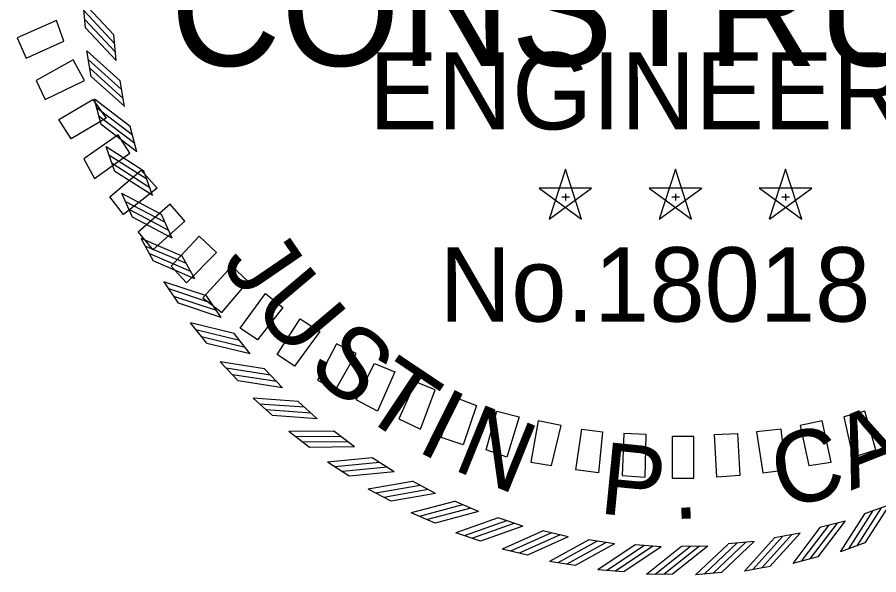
# Model space of a CAD drawing. Extents: x 16 to 1228743, y 11 to 152440.
# Drawn here: x 17.6697 to 17.7949, y 10.8149 to 10.8959 of the extents above; entities that cross this region are included whole.
import ezdxf

# ---------------------------------------------------------------- set-up
doc = ezdxf.new("R2010")
doc.units = 0
doc.layers.add('STAMP_JUSTIN', color=7, linetype='Continuous')
doc.layers.add('STAMP_PRELIM', color=7, linetype='Continuous')

msp = doc.modelspace()

# ---------------------------------------------------------------- linework, layer by layer
at = {"layer": 'STAMP_JUSTIN'}
for p, q in [((17.67966, 10.89435), (17.67932, 10.8981)), ((17.68413, 10.88959), (17.68378, 10.89335)), ((17.68051, 10.88729), (17.67985, 10.891)), ((17.68535, 10.88292), (17.6847, 10.88664)), ((17.68193, 10.88033), (17.68097, 10.88397)), ((17.68712, 10.87637), (17.68616, 10.88003)), ((17.68392, 10.87351), (17.68267, 10.87706)), ((17.68942, 10.86999), (17.68816, 10.87356)), ((17.74939, 10.87381), (17.74703, 10.86658)), ((17.75174, 10.86658), (17.74939, 10.87382)), ((17.76538, 10.87381), (17.76302, 10.86658)), ((17.76773, 10.86658), (17.76539, 10.87382)), ((17.78137, 10.87381), (17.77901, 10.86658)), ((17.78372, 10.86658), (17.78138, 10.87382)), ((17.75319, 10.87105), (17.74558, 10.87106)), ((17.74559, 10.87105), (17.75174, 10.86657)), ((17.74704, 10.86658), (17.7532, 10.87105)), ((17.76918, 10.87105), (17.76157, 10.87106)), ((17.76158, 10.87105), (17.76773, 10.86657)), ((17.76303, 10.86658), (17.76919, 10.87105)), ((17.78517, 10.87105), (17.77756, 10.87106)), ((17.77757, 10.87105), (17.78372, 10.86657)), ((17.77902, 10.86658), (17.78518, 10.87105)), ((17.68647, 10.86687), (17.68493, 10.87031)), ((17.74885, 10.86983), (17.74998, 10.86983)), ((17.7494, 10.87024), (17.7494, 10.86928)), ((17.76484, 10.86983), (17.76597, 10.86983)), ((17.76539, 10.87024), (17.76539, 10.86928)), ((17.78083, 10.86983), (17.78196, 10.86983)), ((17.78138, 10.87024), (17.78138, 10.86928)), ((17.69224, 10.86383), (17.69069, 10.86727)), ((17.68956, 10.86047), (17.68774, 10.86377)), ((17.69556, 10.85791), (17.69373, 10.86122)), ((17.69317, 10.85435), (17.69108, 10.85749)), ((17.69936, 10.85229), (17.69726, 10.85544)), ((17.69727, 10.84855), (17.69492, 10.8515)), ((17.70361, 10.84701), (17.70126, 10.84997)), ((17.70183, 10.8431), (17.69925, 10.84585)), ((17.70828, 10.84209), (17.70569, 10.84485)), ((17.70683, 10.83805), (17.70403, 10.84058)), ((17.71334, 10.83758), (17.71054, 10.84011)), ((17.71223, 10.83343), (17.70923, 10.83572)), ((17.71875, 10.83349), (17.71575, 10.83579)), ((17.71799, 10.82927), (17.71482, 10.8313)), ((17.72449, 10.82987), (17.72131, 10.83191)), ((17.7305, 10.82674), (17.72716, 10.82851)), ((17.72408, 10.8256), (17.72075, 10.82736)), ((17.73676, 10.82411), (17.73328, 10.8256)), ((17.7964, 10.82504), (17.79284, 10.82378)), ((17.73045, 10.82245), (17.72698, 10.82393)), ((17.7432, 10.82201), (17.73962, 10.8232)), ((17.79002, 10.82274), (17.78637, 10.82178)), ((17.73705, 10.81983), (17.73348, 10.82102)), ((17.7498, 10.82045), (17.74613, 10.82134)), ((17.78348, 10.82097), (17.77976, 10.82032)), ((17.75651, 10.81944), (17.75278, 10.82002)), ((17.77681, 10.81975), (17.77304, 10.81941)), ((17.74386, 10.81777), (17.74019, 10.81866)), ((17.76328, 10.81898), (17.75951, 10.81926)), ((17.77006, 10.81909), (17.76628, 10.81905)), ((17.79289, 10.81955), (17.78934, 10.81829)), ((17.78607, 10.81755), (17.78242, 10.81659)), ((17.7508, 10.81627), (17.74708, 10.81686)), ((17.77911, 10.81613), (17.77539, 10.81548)), ((17.75785, 10.81536), (17.75409, 10.81564)), ((17.76495, 10.81503), (17.76118, 10.81499)), ((17.77205, 10.81529), (17.7683, 10.81494))]:
    msp.add_line(p, q, dxfattribs=at)
for points in [[(17.68378, 10.89335), (17.67932, 10.8981)], [(17.68389, 10.8921), (17.67942, 10.89685)], [(17.68404, 10.8908), (17.67957, 10.89555)], [(17.68414, 10.88959), (17.67967, 10.89434)], [(17.68469, 10.88664), (17.67985, 10.89101)], [(17.6849, 10.8854), (17.68006, 10.88977)], [(17.68516, 10.88411), (17.68031, 10.88848)], [(17.68536, 10.88292), (17.68051, 10.88729)], [(17.68616, 10.88002), (17.68097, 10.88398)], [(17.68646, 10.8788), (17.68128, 10.88276)], [(17.68683, 10.87755), (17.68164, 10.8815)], [(17.68712, 10.87637), (17.68194, 10.88032)], [(17.68816, 10.87355), (17.68266, 10.87706)], [(17.68857, 10.87236), (17.68307, 10.87588)], [(17.68903, 10.87114), (17.68353, 10.87465)], [(17.68943, 10.86999), (17.68393, 10.8735)], [(17.69069, 10.86727), (17.68492, 10.87031)], [(17.6912, 10.86612), (17.68543, 10.86916)], [(17.69176, 10.86494), (17.68599, 10.86798)], [(17.69225, 10.86382), (17.68648, 10.86687)], [(17.69373, 10.86121), (17.68773, 10.86377)], [(17.69433, 10.86011), (17.68833, 10.86267)], [(17.69499, 10.85898), (17.68899, 10.86154)], [(17.69557, 10.85791), (17.68957, 10.86047)], [(17.69726, 10.85543), (17.69107, 10.85749)], [(17.69795, 10.85438), (17.69176, 10.85644)], [(17.6987, 10.85331), (17.69251, 10.85536)], [(17.69936, 10.85229), (17.69317, 10.85435)], [(17.70126, 10.84996), (17.69492, 10.8515)], [(17.70203, 10.84897), (17.69569, 10.85051)], [(17.70287, 10.84796), (17.69653, 10.8495)], [(17.70361, 10.84701), (17.69727, 10.84854)], [(17.70569, 10.84484), (17.69925, 10.84585)], [(17.70654, 10.84392), (17.7001, 10.84493)], [(17.70746, 10.84298), (17.70102, 10.84399)], [(17.70828, 10.84209), (17.70184, 10.8431)], [(17.71054, 10.8401), (17.70403, 10.84058)], [(17.71146, 10.83925), (17.70495, 10.83973)], [(17.71245, 10.8384), (17.70595, 10.83887)], [(17.71334, 10.83758), (17.70684, 10.83805)], [(17.71575, 10.83578), (17.70923, 10.83572)], [(17.71674, 10.83501), (17.71022, 10.83495)], [(17.7178, 10.83424), (17.71128, 10.83417)], [(17.71876, 10.83349), (17.71224, 10.83343)], [(17.72131, 10.83191), (17.71481, 10.8313)], [(17.72236, 10.83122), (17.71587, 10.83062)], [(17.72348, 10.83054), (17.71698, 10.82993)], [(17.72449, 10.82987), (17.718, 10.82927)], [(17.72717, 10.8285), (17.72074, 10.82736)], [(17.72827, 10.82791), (17.72185, 10.82677)], [(17.72944, 10.82732), (17.72302, 10.82618)], [(17.73051, 10.82674), (17.72409, 10.8256)], [(17.73328, 10.82559), (17.72698, 10.82393)], [(17.73443, 10.82509), (17.72813, 10.82342)], [(17.79641, 10.82505), (17.79289, 10.81955)], [(17.73565, 10.8246), (17.72934, 10.82294)], [(17.73676, 10.82411), (17.73045, 10.82245)], [(17.79285, 10.82378), (17.78933, 10.81828)], [(17.79403, 10.82419), (17.79052, 10.81869)], [(17.79526, 10.82465), (17.79175, 10.81916)], [(17.73962, 10.8232), (17.73347, 10.82102)], [(17.74081, 10.82279), (17.73466, 10.82061)], [(17.74206, 10.82241), (17.73591, 10.82023)], [(17.78885, 10.82245), (17.7849, 10.81726)], [(17.79003, 10.82275), (17.78607, 10.81756)], [(17.74321, 10.82201), (17.73706, 10.81983)], [(17.74614, 10.82134), (17.74019, 10.81866)], [(17.74735, 10.82103), (17.74141, 10.81835)], [(17.78348, 10.82098), (17.77911, 10.81613)], [(17.78637, 10.82178), (17.78242, 10.81659)], [(17.78759, 10.82209), (17.78364, 10.8169)], [(17.74863, 10.82075), (17.74269, 10.81807)], [(17.74981, 10.82045), (17.74386, 10.81777)], [(17.75278, 10.82002), (17.74707, 10.81686)], [(17.75402, 10.81981), (17.74831, 10.81665)], [(17.77681, 10.81976), (17.77206, 10.81529)], [(17.77976, 10.82032), (17.77539, 10.81547)], [(17.781, 10.82052), (17.77663, 10.81568)], [(17.78228, 10.82078), (17.77791, 10.81593)], [(17.75532, 10.81964), (17.74961, 10.81648)], [(17.75651, 10.81944), (17.75081, 10.81628)], [(17.75951, 10.81926), (17.75409, 10.81563)], [(17.76076, 10.81915), (17.75534, 10.81553)], [(17.76207, 10.81909), (17.75665, 10.81546)], [(17.76328, 10.81899), (17.75786, 10.81536)], [(17.76628, 10.81905), (17.76118, 10.81499)], [(17.76754, 10.81905), (17.76243, 10.81499)], [(17.76885, 10.81909), (17.76374, 10.81503)], [(17.77006, 10.81909), (17.76495, 10.81503)], [(17.77305, 10.8194), (17.76829, 10.81494)], [(17.7743, 10.81951), (17.76954, 10.81504)], [(17.7756, 10.81966), (17.77085, 10.81519)]]:
    msp.add_lwpolyline(points, dxfattribs=at)
at = {"layer": 'STAMP_PRELIM'}
for p, q in [((17.67544, 10.89542), (17.66975, 10.8929)), ((17.67651, 10.89241), (17.67544, 10.89542)), ((17.66975, 10.8929), (17.67105, 10.88997)), ((17.67105, 10.88997), (17.67651, 10.89241)), ((17.67788, 10.88972), (17.67251, 10.88672)), ((17.67951, 10.88672), (17.67788, 10.88972)), ((17.67251, 10.88672), (17.67382, 10.88395)), ((17.67382, 10.88395), (17.67951, 10.88672)), ((17.67577, 10.88102), (17.68074, 10.88395)), ((17.68074, 10.88395), (17.68269, 10.88126)), ((17.68269, 10.88126), (17.67756, 10.87825)), ((17.67756, 10.87825), (17.67577, 10.88102)), ((17.68439, 10.87882), (17.67944, 10.87532)), ((17.68611, 10.87614), (17.68439, 10.87882)), ((17.68098, 10.87247), (17.68611, 10.87614)), ((17.67944, 10.87532), (17.68098, 10.87247)), ((17.68318, 10.86979), (17.68774, 10.8737)), ((17.68774, 10.8737), (17.69009, 10.87109)), ((17.69009, 10.87109), (17.68521, 10.86726)), ((17.68521, 10.86726), (17.68318, 10.86979)), ((17.69197, 10.86873), (17.68732, 10.86466)), ((17.69408, 10.86628), (17.69197, 10.86873)), ((17.68944, 10.86214), (17.69408, 10.86628)), ((17.68732, 10.86466), (17.68944, 10.86214)), ((17.69213, 10.85977), (17.6962, 10.86409)), ((17.6962, 10.86409), (17.69872, 10.86173)), ((17.69872, 10.86173), (17.69432, 10.85733)), ((17.69432, 10.85733), (17.69213, 10.85977)), ((17.70092, 10.85977), (17.69669, 10.85514)), ((17.70328, 10.8575), (17.70092, 10.85977)), ((17.69946, 10.85302), (17.70328, 10.8575)), ((17.69669, 10.85514), (17.69946, 10.85302)), ((17.70214, 10.85075), (17.7058, 10.85579)), ((17.7058, 10.85579), (17.70832, 10.85375)), ((17.70832, 10.85375), (17.70466, 10.84903)), ((17.70751, 10.84692), (17.71085, 10.85212)), ((17.71085, 10.85212), (17.71369, 10.85026)), ((17.70466, 10.84903), (17.70214, 10.85075)), ((17.71369, 10.85026), (17.71004, 10.84521)), ((17.71613, 10.84847), (17.71337, 10.84317)), ((17.71899, 10.84708), (17.71613, 10.84847)), ((17.71004, 10.84521), (17.70751, 10.84692)), ((17.71597, 10.84179), (17.71899, 10.84708)), ((17.71899, 10.84033), (17.72167, 10.84561)), ((17.72167, 10.84561), (17.7246, 10.8444)), ((17.7246, 10.8444), (17.72208, 10.8387)), ((17.71337, 10.84317), (17.71597, 10.84179)), ((17.72761, 10.84293), (17.72517, 10.83756)), ((17.73046, 10.84179), (17.72761, 10.84293)), ((17.72834, 10.8361), (17.73046, 10.84179)), ((17.72208, 10.8387), (17.71899, 10.84033)), ((17.73136, 10.83487), (17.73331, 10.84073)), ((17.73331, 10.84073), (17.73648, 10.83952)), ((17.73648, 10.83952), (17.73452, 10.83382)), ((17.73787, 10.83308), (17.73941, 10.8387)), ((17.73941, 10.8387), (17.74266, 10.83789)), ((17.79288, 10.8387), (17.78986, 10.83789)), ((17.79451, 10.83308), (17.79288, 10.8387)), ((17.72517, 10.83756), (17.72834, 10.8361)), ((17.74266, 10.83789), (17.74087, 10.83203)), ((17.74543, 10.83731), (17.74438, 10.83129)), ((17.74877, 10.83659), (17.74543, 10.83731)), ((17.7867, 10.83731), (17.78352, 10.83659)), ((17.788, 10.83129), (17.7867, 10.83731)), ((17.78986, 10.83789), (17.79117, 10.83203)), ((17.74738, 10.8308), (17.74877, 10.83659)), ((17.75089, 10.83015), (17.75178, 10.8361)), ((17.75178, 10.8361), (17.75479, 10.83569)), ((17.78075, 10.8361), (17.77717, 10.83569)), ((17.7814, 10.83015), (17.78075, 10.8361)), ((17.78352, 10.83659), (17.78474, 10.8308)), ((17.73452, 10.83382), (17.73136, 10.83487)), ((17.75479, 10.83569), (17.75422, 10.82975)), ((17.75789, 10.83545), (17.75764, 10.82934)), ((17.76114, 10.83528), (17.75789, 10.83545)), ((17.76098, 10.8291), (17.76114, 10.83528)), ((17.76489, 10.83503), (17.76489, 10.82894)), ((17.76805, 10.83503), (17.76489, 10.83503)), ((17.76805, 10.82894), (17.76805, 10.83503)), ((17.77107, 10.83528), (17.7744, 10.83545)), ((17.7714, 10.8291), (17.77107, 10.83528)), ((17.7744, 10.83545), (17.77473, 10.82934)), ((17.77717, 10.83569), (17.77807, 10.82975)), ((17.74087, 10.83203), (17.73787, 10.83308)), ((17.79117, 10.83203), (17.79451, 10.83308)), ((17.74438, 10.83129), (17.74738, 10.8308)), ((17.78474, 10.8308), (17.788, 10.83129)), ((17.75422, 10.82975), (17.75089, 10.83015)), ((17.77807, 10.82975), (17.7814, 10.83015)), ((17.75764, 10.82934), (17.76098, 10.8291)), ((17.76489, 10.82894), (17.76805, 10.82894)), ((17.77473, 10.82934), (17.7714, 10.8291))]:
    msp.add_line(p, q, dxfattribs=at)

# ---------------------------------------------------------------- texts
at = {"layer": 'STAMP_JUSTIN'}
for s, height, p in [('ENGINEER', 0.011194, (17.72085, 10.87961)), ('No.18018', 0.010794, (17.73109, 10.8517))]:
    msp.add_text(s, height=height, dxfattribs=at).set_placement(p)
for s, rotation, p in [('J', 304.3679, (17.69921, 10.8603)), ('U', 310.2047, (17.70369, 10.85374)), ('S', 318.9599, (17.71161, 10.84484)), ('T', 326.256, (17.71918, 10.83842)), ('I', 333.552, (17.7275, 10.83301)), ('N', 337.9296, (17.7328, 10.83029)), ('A', 21.7056, (17.79088, 10.82715)), ('C', 14.0448, (17.78081, 10.82446)), ('P', 354.3456, (17.75413, 10.82386)), ('.', 2.3712, (17.76501, 10.823))]:
    msp.add_text(s, height=0.01042, rotation=rotation, dxfattribs=at).set_placement(p)
at = {"layer": 'STAMP_PRELIM'}
msp.add_text('CONSTRUCTION', height=0.0166586, dxfattribs=at).set_placement((17.69196, 10.88883))

doc.saveas('drawing.dxf')
